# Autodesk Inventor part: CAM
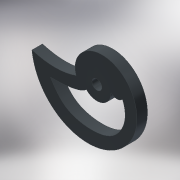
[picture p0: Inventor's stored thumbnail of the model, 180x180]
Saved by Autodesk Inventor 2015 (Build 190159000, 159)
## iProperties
Created: 2014-08
Part Number: CAM
Material: Iron, Cast
Document SubType Name: Modeling
Designer: lakshayg
Density: 7.15 g/cm^3
Appearance: Iron Gray
Mass: 507.087 g
Surface Area: 193.871 cm^2
Volume: 70.9213 cm^3
Author: lakshayg
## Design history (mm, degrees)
sketch "Sketch1"
  geometry: C1 r 6 at (0, 0); 4 further points
  constraints: 1 centre point, 1 coincident, 1 horizontal alignment, 7 other
  dimensions: "d0" = 12 diameter of C1
extrude "Extrusion1" new body sketch "Sketch1" distance "d5" = 12.7; taper "d6" = 0 deg
node "Midplane"
node "Hole-Plane"
sketch "Sketch3"
  geometry: L1 (-12.64, 11.408)-(-21.426, 20.076); L2 (-21.426, 20.076)-(-56.082, 20.076); L3 (-56.082, 20.076)-(-46.089, 36.637); L4 (-46.089, 36.637)-(-33.24, 47.202); L5 (-33.24, 47.202)-(-10.968, 52.056); L6 (-10.968, 52.056)-(16.157, 49.486); L7 (16.157, 49.486)-(29.577, 36.923); L8 (29.577, 36.923)-(37.287, 15.328); L9 (37.287, 15.328)-(30.828, 0); L10 (30.828, 0)-(24.631, 6); L11 (24.631, 6)-(17.027, 0); C1 r 6 at (0, 0) reference; A1 r 17.027 centre (0, 0) between (17.027, 0) and (-12.64, 11.408); 3 further points
  constraints: 2 point on circle, 1 centre point, 1 coincident, 1 horizontal, 1 horizontal alignment, 9 other
extrude "Extrusion4" cut sketch "Sketch3" distance "d15" = 12.75; taper "d16" = 0 deg
body "Solid1"
node "2D Equation Curve1" dims "d3" = 0, "d4" = 10
other parameters: "d7" = 0
